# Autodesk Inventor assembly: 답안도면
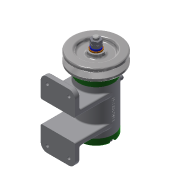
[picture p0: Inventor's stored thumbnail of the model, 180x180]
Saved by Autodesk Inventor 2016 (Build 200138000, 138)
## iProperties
Created: 2017-02
Part Number: 답안도면
Material: 일반
Document SubType Name: Assembly
Designer: CAMTIC
Author: CAMTIC
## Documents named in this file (16)
- C:\Users\CAMTIC\Desktop\470207V1017\답안도면.iam
- C:\Users\CAMTIC\Desktop\470207V1017\본체.ipt
- C:\Users\CAMTIC\Desktop\470207V1017\470207V1017\축.ipt
- C:\Users\CAMTIC\Desktop\470207V1017\470207V1017\키 3 x 3 x 12.ipt
- C:\Users\CAMTIC\Desktop\470207V1017\470207V1017\베어링 15 x 32 x 9.ipt
- C:\Users\CAMTIC\Desktop\470207V1017\470207V1017\V벨트풀리.ipt
- C:\Users\CAMTIC\Desktop\470207V1017\470207V1017\너트 M 8.ipt
- C:\Users\CAMTIC\Desktop\470207V1017\470207V1017\니플 M 6 x 0.75.ipt
- C:\Users\CAMTIC\Desktop\470207V1017\470207V1017\뒤커버.ipt
- C:\Users\CAMTIC\Desktop\470207V1017\470207V1017\볼트 M 6 x 8.ipt
- C:\Users\CAMTIC\Desktop\470207V1017\470207V1017\볼트 M4 x 12.ipt
- C:\Users\CAMTIC\Desktop\470207V1017\470207V1017\스프링와셔 8.ipt
- C:\Users\CAMTIC\Desktop\470207V1017\470207V1017\앞커버.ipt
- C:\Users\CAMTIC\Desktop\470207V1017\470207V1017\오일 실 15 25 7.ipt
- C:\Users\CAMTIC\Desktop\470207V1017\470207V1017\와셔 6x11.5.ipt
- C:\Users\CAMTIC\Desktop\470207V1017\470207V1017\와셔 8x17.ipt
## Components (11 placed, 3 different names)
1. KS B 2023 6002 - 15 x 32 x 9:1
2. KS B 2023 6002 - 15 x 32 x 9:2
3. V벨트풀리:1
4. ISO 4762 M4 x 12:2
5. ISO 4762 M4 x 12:3
6. ISO 4762 M4 x 12:4
7. ISO 4762 M4 x 12:5
8. ISO 4762 M4 x 12:1
9. ISO 4762 M4 x 12:6
10. ISO 4762 M4 x 12:7
11. ISO 4762 M4 x 12:8
